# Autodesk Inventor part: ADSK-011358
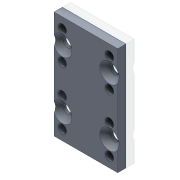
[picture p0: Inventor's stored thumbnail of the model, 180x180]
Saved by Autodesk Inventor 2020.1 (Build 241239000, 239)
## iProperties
Created: 1999-12
Part Number: ADSK-011358
Material: Pearson Aluminium
Description: PLT-XX,FA,CP,03,030,051,PLATE,CLAMP
Document SubType Name: Modeling
Designer: sspink
Density: 2.71 g/cm^3
Appearance: Pearson-Aluminum
Mass: 240.995 g
Surface Area: 258.363 cm^2
Volume: 88.9279 cm^3
Control State: 0
Checked Out: False
Master: False
Shininess: 35.0
Length Units: 11269
Angle Units: 11279
Time Units: 11290
Mass Units: 11283
Length Display Precision: 3
Angle Display Precision: 2
Compacted: True
Dimensions: 77x130x10 mm
Mass: 0,241 kg
DocNumber: ADSK-011358.ipt
Folder: 01 - Themengebiete\Simplification\01 - Packaging machine\
VDS_Category: 3D Komponenten
Density: 2.71
Volumn: 82.28292120831077
Area: 251.96808906259037
PropertySet Name: Model Information
Author: sspink
Revision Number: -
Title: plate
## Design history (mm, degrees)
workplane "Arbeitsebene1"
node "Solide1"
  node "Extrusion1" dims "d6" = 10, "d7" = 0
  node "Hole1" dims "d14" = 9, "d15" = 19, "d16" = 6.35, "d17" = 90 deg, "d18" = 19.05, "d19" = 118 deg, "d40" = 6
  node "Hole2" dims "d22" = 10.31875, "d23" = 19.3548, "d24" = 6.35, "d25" = 60 deg, "d26" = 19.05, "d27" = 118 deg
sketch "Sketch1"
  geometry: L1 (0, 0)-(0, 130) reference; L2 (0, 0)-(-77, 0) reference; L3 (-77, 0)-(-77, 130); L4 (-77, 130)-(0, 130)
  constraints: 8 end point, 3 perpendicular, 1 horizontal, 1 vertical
  dimensions: "d0" = 77 distance of L3.end L1.end; "d1" = 130 distance of L2.end L3.end
sketch "Sketch2"
  geometry: L1 (0, 0)-(-77, 0) reference; L2 (-77, 0)-(-77, 130) reference; L3 (-67, 30)-(-10, 30); L4 (-10, 30)-(-10, 100); L5 (-10, 100)-(-67, 100); L6 (-67, 100)-(-67, 30); C1 r 3.746 at (-10, 100); C2 r 3.746 at (-10, 30); 6 further points
  constraints: 8 end point, 4 midpoint, 3 coincident, 3 horizontal alignment, 2 centre point, 2 parallel, 1 horizontal, 1 perpendicular, 1 vertical alignment
  dimensions: "d34" = 70 distance of L5.end L3.start; "d35" = 57 distance of L4.end L5.end
sketch "Sketch3"
  geometry: L1 (-67, 12.52)-(-67, 117.52); L2 (-10, 12.52)-(-10, 117.52); L3 (-67, 12.52)-(-10, 12.52); L4 (-67, 117.52)-(-10, 117.52); L5 (0, 0)-(-77, 0) reference; L6 (-77, 36.169)-(-77, 93.871) reference; 8 further points
  constraints: 8 end point, 7 vertical alignment, 5 horizontal alignment, 4 midpoint, 2 vertical, 1 parallel, 1 perpendicular
  dimensions: "d36" = 57 distance of L1.start L2.start; "d37" = 105 distance of L1.start L1.end; "d38" = 35 distance of L1.start point (-67, 47.52) (= 0.333333 x d37); "d39" = 35 distance from line of L4 point (-67, 82.52) (= 0.333333 x d37)
node "Corps solides"
node "Corps surfaciques"
